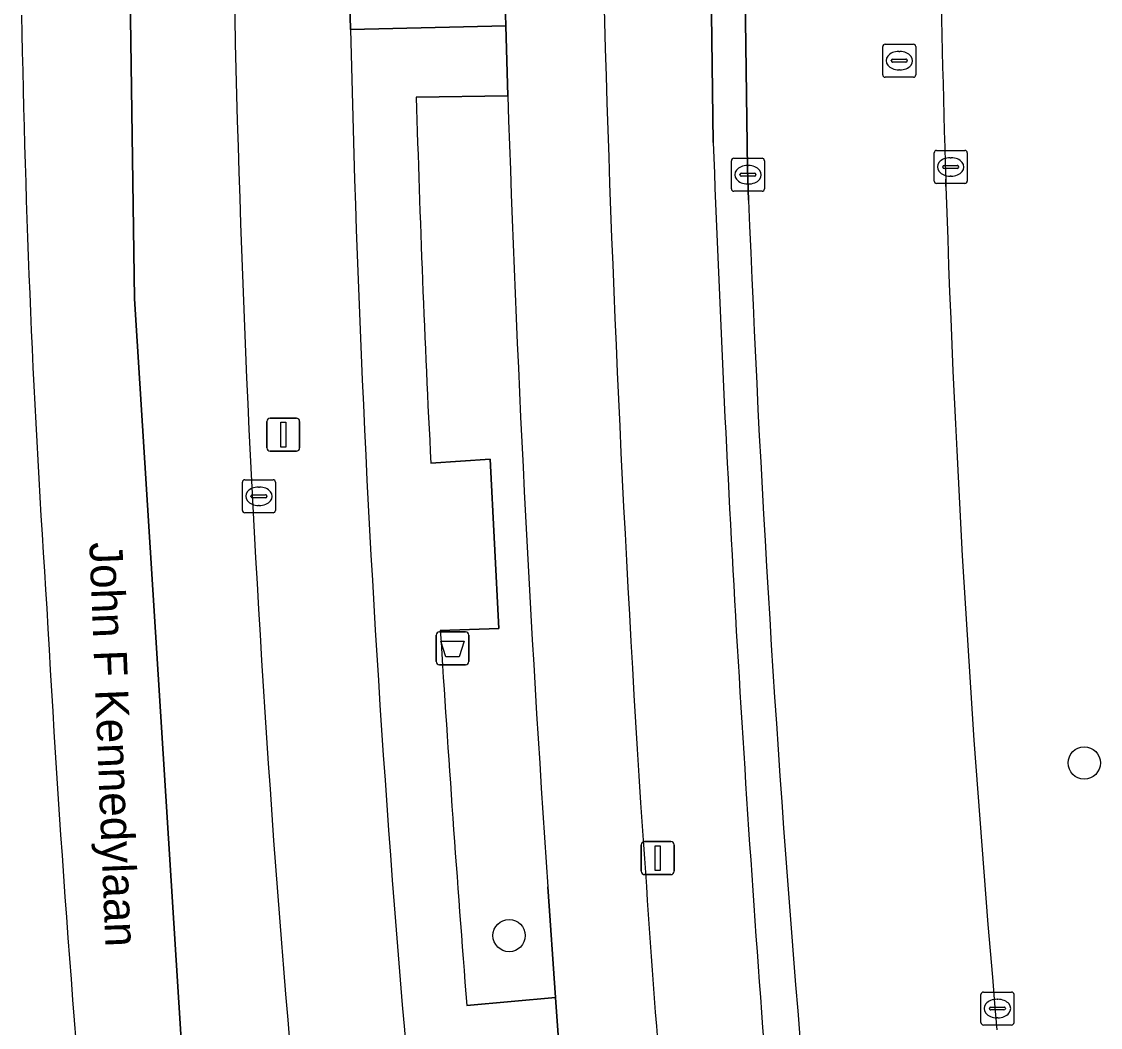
# Model space of a CAD drawing. Extents: x 161477 to 163040, y 383680 to 384871.
# Drawn here: x 161509.36 to 161542, y 384062.14 to 384092.59 of the extents above; entities that cross this region are included whole.
import ezdxf

# ---------------------------------------------------------------- set-up
doc = ezdxf.new("R2010")
doc.units = 0
for name, color, linetype in [('IMGEO_Afvalbak', 7, 'Continuous'), ('IMGEO_Berm_groen', 7, 'Continuous'), ('IMGEO_Boom', 7, 'Continuous'), ('IMGEO_Fietspad_open', 7, 'Continuous'), ('IMGEO_Groenvoorziening', 7, 'Continuous'), ('IMGEO_Kolk', 7, 'Continuous'), ('IMGEO_Lichtmast', 7, 'Continuous'), ('IMGEO_Openbare_ruimte_label', 7, 'Continuous'), ('IMGEO_OVBaan_gesloten', 7, 'Continuous'), ('IMGEO_Rijbaan_lokaal_gesloten', 7, 'Continuous'), ('IMGEO_Rijbaan_lokaal_open', 7, 'Continuous'), ('IMGEO_Rioolput', 7, 'Continuous'), ('IMGEO_Verkeerseiland_groen', 7, 'Continuous'), ('IMGEO_Voetpad_open', 7, 'Continuous')]:
    doc.layers.add(name, color=color, linetype=linetype)

msp = doc.modelspace()

# ---------------------------------------------------------------- linework, layer by layer
at = {"layer": 'IMGEO_Afvalbak'}
for p, q in [((161522.002, 384074.118), (161522.792, 384074.118)), ((161522.792, 384074.118), (161522.002, 384074.118)), ((161521.902, 384073.218), (161521.902, 384074.018)), ((161521.902, 384074.018), (161521.902, 384073.218)), ((161522.892, 384074.018), (161522.892, 384073.218)), ((161522.892, 384073.218), (161522.892, 384074.018)), ((161522.792, 384073.118), (161522.002, 384073.118)), ((161522.002, 384073.118), (161522.792, 384073.118))]:
    msp.add_line(p, q, dxfattribs=at)
msp.add_lwpolyline([(161522.045, 384073.832), (161522.749, 384073.832), (161522.6, 384073.362), (161522.194, 384073.362), (161522.045, 384073.832)], dxfattribs=at)
for centre, start, end in [((161522.002, 384074.018), 90, 180), ((161522.002, 384074.018), 90, 180), ((161522.792, 384074.018), 0, 90), ((161522.792, 384074.018), 360, 90), ((161522.002, 384073.218), 180, 270), ((161522.002, 384073.218), 180, 270), ((161522.792, 384073.218), 270, 0), ((161522.792, 384073.218), 270, 0)]:
    msp.add_arc(centre, 0.1, start, end, dxfattribs=at)
at = {"layer": 'IMGEO_Berm_groen'}
msp.add_lwpolyline([(161519.286, 384093.326), (161519.293, 384093.147), (161519.31, 384092.356), (161524.006, 384092.467), (161523.996, 384092.805), (161523.824, 384101.994)], dxfattribs=at)
for centre, radius, start, end in [((161870.69, 384099.146), 361.389, 181.00836, 183.85803), ((162020.3, 384102.502), 510.93, 183.10469, 185.34779)]:
    msp.add_arc(centre, radius, start, end, dxfattribs=at)
at = {"layer": 'IMGEO_Boom'}
for centre in [(161541.513, 384070.146), (161524.109, 384064.919)]:
    msp.add_circle(centre, 0.489, dxfattribs=at)
at = {"layer": 'IMGEO_Fietspad_open'}
for points in [[(161515.721, 384110.468), (161523.848, 384110.651), (161523.758, 384107.222), (161523.769, 384107.113), (161523.788, 384106.113), (161523.681, 384106.114), (161523.824, 384101.994), (161523.996, 384092.805), (161524.006, 384092.467), (161524.071, 384090.349)], [(161525.28, 384066.396), (161525.511, 384063.044), (161525.665, 384060.913)]]:
    msp.add_lwpolyline(points, dxfattribs=at)
for centre, radius, start, end in [((162194.711, 384111.674), 667.99, 181.427877, 183.668064), ((162190.499, 384111.979), 666.779, 181.85899, 183.919982), ((162521.881, 384135.354), 996.008, 183.823363, 185.383124)]:
    msp.add_arc(centre, radius, start, end, dxfattribs=at)
at = {"layer": 'IMGEO_Groenvoorziening'}
for points in [[(161531.356, 384087.19), (161531.32, 384088.12), (161531.174, 384099.384), (161530.14, 384099.502), (161530.155, 384099.073), (161530.287, 384088.932)], [(161537.32, 384087.82), (161537.327, 384087.599)]]:
    msp.add_lwpolyline(points, dxfattribs=at)
for centre, radius, start, end in [((162047.346, 384103.272), 510.26, 179.99265, 181.73528), ((162231.505, 384114.608), 701.688, 182.097053, 184.515444), ((161984.51, 384101.846), 447.41, 181.82484, 185.10092), ((162116.096, 384110.255), 585.195, 182.258894, 184.745135)]:
    msp.add_arc(centre, radius, start, end, dxfattribs=at)
at = {"layer": 'IMGEO_Kolk'}
for p, q in [((161530.911, 384088.455), (161531.763, 384088.455)), ((161536.97, 384087.765), (161536.97, 384088.617)), ((161537.045, 384088.691), (161537.897, 384088.691)), ((161537.458, 384088.471), (161537.483, 384088.471)), ((161537.971, 384088.617), (161537.971, 384087.765)), ((161530.836, 384087.529), (161530.836, 384088.381)), ((161531.324, 384088.235), (161531.349, 384088.235)), ((161531.837, 384088.381), (161531.837, 384087.529)), ((161537.229, 384088.185), (161537.229, 384088.197)), ((161537.667, 384088.148), (161537.269, 384088.148)), ((161537.272, 384088.234), (161537.67, 384088.234)), ((161537.713, 384088.197), (161537.713, 384088.185)), ((161531.095, 384087.949), (161531.095, 384087.961)), ((161531.533, 384087.912), (161531.135, 384087.912)), ((161531.138, 384087.998), (161531.536, 384087.998)), ((161531.579, 384087.961), (161531.579, 384087.949)), ((161537.481, 384087.911), (161537.456, 384087.911)), ((161531.347, 384087.675), (161531.322, 384087.675)), ((161537.897, 384087.691), (161537.045, 384087.691)), ((161531.763, 384087.455), (161530.911, 384087.455)), ((161516.039, 384077.794), (161516.039, 384078.646)), ((161516.114, 384078.72), (161516.966, 384078.72)), ((161517.04, 384078.646), (161517.04, 384077.794)), ((161516.527, 384078.5), (161516.552, 384078.5)), ((161516.298, 384078.214), (161516.298, 384078.226)), ((161516.736, 384078.177), (161516.338, 384078.177)), ((161516.341, 384078.263), (161516.739, 384078.263)), ((161516.782, 384078.226), (161516.782, 384078.214)), ((161516.966, 384077.72), (161516.114, 384077.72)), ((161516.55, 384077.94), (161516.525, 384077.94)), ((161538.386, 384062.285), (161538.386, 384063.137)), ((161538.461, 384063.211), (161539.313, 384063.211)), ((161538.874, 384062.991), (161538.899, 384062.991)), ((161539.387, 384063.137), (161539.387, 384062.285)), ((161538.645, 384062.705), (161538.645, 384062.717)), ((161539.083, 384062.668), (161538.685, 384062.668)), ((161538.688, 384062.754), (161539.086, 384062.754)), ((161539.129, 384062.717), (161539.129, 384062.705)), ((161538.897, 384062.431), (161538.872, 384062.431)), ((161539.313, 384062.211), (161538.461, 384062.211))]:
    msp.add_line(p, q, dxfattribs=at)
for points in [[(161530.911, 384088.455), (161531.763, 384088.455)], [(161536.97, 384087.765), (161536.97, 384088.617)], [(161537.045, 384088.691), (161537.897, 384088.691)], [(161537.971, 384088.617), (161537.971, 384087.765)], [(161530.836, 384087.529), (161530.836, 384088.381)], [(161531.837, 384088.381), (161531.837, 384087.529)], [(161537.897, 384087.691), (161537.045, 384087.691)], [(161531.763, 384087.455), (161530.911, 384087.455)], [(161516.039, 384077.794), (161516.039, 384078.646)], [(161516.114, 384078.72), (161516.966, 384078.72)], [(161517.04, 384078.646), (161517.04, 384077.794)], [(161516.966, 384077.72), (161516.114, 384077.72)], [(161538.386, 384062.285), (161538.386, 384063.137)], [(161538.461, 384063.211), (161539.313, 384063.211)], [(161539.387, 384063.137), (161539.387, 384062.285)], [(161539.313, 384062.211), (161538.461, 384062.211)]]:
    msp.add_lwpolyline(points, dxfattribs=at)
for centre, radius, start, end in [((161530.913, 384088.379), 0.0765, 91.552, 178.448), ((161530.913, 384088.379), 0.0765, 91.552, 178.448), ((161531.761, 384088.379), 0.0765, 1.552, 88.448), ((161531.761, 384088.379), 0.0765, 1.552, 88.448), ((161537.047, 384088.615), 0.0765, 91.552, 178.448), ((161537.047, 384088.615), 0.0765, 91.552, 178.448), ((161537.895, 384088.615), 0.0765, 1.552, 88.448), ((161537.895, 384088.615), 0.0765, 1.552, 88.448), ((161537.269, 384088.194), 0.0403, 85.8775, 175.7526), ((161537.266, 384088.184), 0.0366, 178.938, 274.7102), ((161537.67, 384088.191), 0.043, 264.8664, 352.4533), ((161537.674, 384088.196), 0.0386, 1.7309, 96.639), ((161531.135, 384087.958), 0.0403, 85.8775, 175.7526), ((161531.132, 384087.948), 0.0366, 178.938, 274.7102), ((161531.536, 384087.955), 0.043, 264.8664, 352.4533), ((161531.54, 384087.96), 0.0386, 1.7309, 96.639), ((161530.913, 384087.531), 0.0765, 181.552, 268.448), ((161530.913, 384087.531), 0.0765, 181.552, 268.448), ((161531.761, 384087.531), 0.0765, 271.552, 358.448), ((161531.761, 384087.531), 0.0765, 271.552, 358.448), ((161537.047, 384087.767), 0.0765, 181.552, 268.448), ((161537.047, 384087.767), 0.0765, 181.552, 268.448), ((161537.895, 384087.767), 0.0765, 271.552, 358.448), ((161537.895, 384087.767), 0.0765, 271.552, 358.448), ((161516.116, 384078.644), 0.0765, 91.552, 178.448), ((161516.116, 384078.644), 0.0765, 91.552, 178.448), ((161516.964, 384078.644), 0.0765, 1.552, 88.448), ((161516.964, 384078.644), 0.0765, 1.552, 88.448), ((161516.338, 384078.223), 0.0403, 85.8775, 175.7526), ((161516.335, 384078.213), 0.0366, 178.938, 274.7102), ((161516.739, 384078.22), 0.043, 264.8664, 352.4533), ((161516.743, 384078.225), 0.0386, 1.7309, 96.639), ((161516.116, 384077.796), 0.0765, 181.552, 268.448), ((161516.116, 384077.796), 0.0765, 181.552, 268.448), ((161516.964, 384077.796), 0.0765, 271.552, 358.448), ((161516.964, 384077.796), 0.0765, 271.552, 358.448), ((161538.463, 384063.135), 0.0765, 91.552, 178.448), ((161538.463, 384063.135), 0.0765, 91.552, 178.448), ((161539.311, 384063.135), 0.0765, 1.552, 88.448), ((161539.311, 384063.135), 0.0765, 1.552, 88.448), ((161538.685, 384062.714), 0.0403, 85.8775, 175.7526), ((161538.682, 384062.704), 0.0366, 178.938, 274.7102), ((161539.086, 384062.711), 0.043, 264.8664, 352.4533), ((161539.09, 384062.716), 0.0386, 1.7309, 96.639), ((161538.463, 384062.287), 0.0765, 181.552, 268.448), ((161538.463, 384062.287), 0.0765, 181.552, 268.448), ((161539.311, 384062.287), 0.0765, 271.552, 358.448), ((161539.311, 384062.287), 0.0765, 271.552, 358.448)]:
    msp.add_arc(centre, radius, start, end, dxfattribs=at)
for centre, major_axis, ratio, start_param, end_param in [((161537.457, 384088.191), (-0.387, 0.002), 0.722429, 4.712389, 7.853982), ((161537.482, 384088.191), (-0.39, 0.002), 0.717154, 1.570796, 4.712389), ((161531.323, 384087.955), (-0.387, 0.002), 0.722429, 4.712389, 7.853982), ((161531.348, 384087.955), (-0.39, 0.002), 0.717154, 1.570796, 4.712389), ((161516.526, 384078.22), (-0.387, 0.002), 0.722429, 4.712389, 7.853982), ((161516.551, 384078.22), (-0.39, 0.002), 0.717154, 1.570796, 4.712389), ((161538.873, 384062.711), (-0.387, 0.002), 0.722429, 4.712389, 7.853982), ((161538.898, 384062.711), (-0.39, 0.002), 0.717154, 1.570796, 4.712389)]:
    msp.add_ellipse(centre, major_axis=major_axis, ratio=ratio, start_param=start_param, end_param=end_param, dxfattribs=at)
at = {"layer": 'IMGEO_Lichtmast'}
for p, q in [((161516.781, 384079.687), (161516.781, 384080.487)), ((161516.781, 384080.487), (161516.781, 384079.687)), ((161516.881, 384080.587), (161517.671, 384080.587)), ((161517.671, 384080.587), (161516.881, 384080.587)), ((161517.771, 384080.487), (161517.771, 384079.687)), ((161517.771, 384079.687), (161517.771, 384080.487)), ((161517.671, 384079.587), (161516.881, 384079.587)), ((161516.881, 384079.587), (161517.671, 384079.587)), ((161528.11, 384066.866), (161528.11, 384067.666)), ((161528.11, 384067.666), (161528.11, 384066.866)), ((161528.21, 384067.766), (161529, 384067.766)), ((161529, 384067.766), (161528.21, 384067.766)), ((161529.1, 384067.666), (161529.1, 384066.866)), ((161529.1, 384066.866), (161529.1, 384067.666)), ((161529, 384066.766), (161528.21, 384066.766)), ((161528.21, 384066.766), (161529, 384066.766))]:
    msp.add_line(p, q, dxfattribs=at)
for points in [[(161517.201, 384080.462), (161517.351, 384080.462), (161517.351, 384079.712), (161517.201, 384079.712), (161517.201, 384080.462)], [(161528.53, 384067.641), (161528.68, 384067.641), (161528.68, 384066.891), (161528.53, 384066.891), (161528.53, 384067.641)]]:
    msp.add_lwpolyline(points, dxfattribs=at)
for centre, start, end in [((161516.881, 384080.487), 90, 180), ((161516.881, 384080.487), 90, 180), ((161517.671, 384080.487), 0, 90), ((161517.671, 384080.487), 360, 90), ((161516.881, 384079.687), 180, 270), ((161516.881, 384079.687), 180, 270), ((161517.671, 384079.687), 270, 0), ((161517.671, 384079.687), 270, 0), ((161528.21, 384067.666), 90, 180), ((161528.21, 384067.666), 90, 180), ((161529, 384067.666), 0, 90), ((161529, 384067.666), 360, 90), ((161528.21, 384066.866), 180, 270), ((161528.21, 384066.866), 180, 270), ((161529, 384066.866), 270, 0), ((161529, 384066.866), 270, 0)]:
    msp.add_arc(centre, 0.1, start, end, dxfattribs=at)
at = {"layer": 'IMGEO_OVBaan_gesloten'}
msp.add_lwpolyline([(161519.31, 384092.356), (161519.293, 384093.147), (161519.286, 384093.326)], dxfattribs=at)
for centre, radius, start, end in [((162006.795, 384103.458), 491.106, 181.16373, 186.98146), ((162003.689, 384103.252), 484.502, 181.28861, 187.02918)]:
    msp.add_arc(centre, radius, start, end, dxfattribs=at)
at = {"layer": 'IMGEO_Rijbaan_lokaal_gesloten'}
for points in [[(161531.069, 384114.824), (161531.071, 384114.592), (161531.061, 384111.456), (161531.125, 384103.186), (161531.174, 384099.384), (161531.32, 384088.12), (161531.356, 384087.19)], [(161511.594, 384054.883), (161513.763, 384035.93), (161515.753, 384021.118), (161516.416, 384015.919), (161516.652, 384013.931), (161519.658, 384016.476), (161516.91, 384036.302), (161514.276, 384060.331), (161512.771, 384084.199), (161512.45, 384106.854)], [(161515.79, 384093.484), (161515.72, 384103.46), (161515.722, 384103.553), (161515.725, 384103.707), (161515.723, 384104.415), (161515.721, 384105.139), (161515.719, 384106.934), (161512.45, 384106.854), (161512.771, 384084.199), (161514.276, 384060.331), (161516.91, 384036.302), (161519.658, 384016.476), (161522.583, 384018.952), (161522.042, 384023.134), (161521.992, 384023.395), (161520.306, 384036.379), (161519.33, 384043.765)], [(161537.327, 384087.599), (161537.32, 384087.82)]]:
    msp.add_lwpolyline(points, dxfattribs=at)
for centre, radius, start, end in [((162047.346, 384103.272), 510.26, 179.99265, 181.73528), ((162006.795, 384103.458), 491.106, 181.16373, 186.98146), ((161870.69, 384099.146), 361.389, 181.00836, 183.85803), ((161984.51, 384101.846), 447.41, 181.82484, 185.10092), ((162116.096, 384110.255), 585.195, 182.258894, 184.745135), ((162020.3, 384102.502), 510.93, 183.10469, 185.34779)]:
    msp.add_arc(centre, radius, start, end, dxfattribs=at)
at = {"layer": 'IMGEO_Rijbaan_lokaal_open'}
for points in [[(161521.302, 384090.299), (161524.071, 384090.349), (161524.006, 384092.467), (161519.31, 384092.356)], [(161523.534, 384079.342), (161521.741, 384079.227)], [(161522.026, 384074.158), (161523.8, 384074.218), (161523.534, 384079.342)], [(161523.373, 384056.802), (161525.156, 384056.968), (161524.851, 384060.863), (161525.665, 384060.913), (161525.511, 384063.044), (161522.828, 384062.803)]]:
    msp.add_lwpolyline(points, dxfattribs=at)
for centre, radius, start, end in [((162003.689, 384103.252), 484.502, 181.28861, 187.02918), ((161990.633, 384103.363), 469.513, 181.59445, 182.94668), ((162296.446, 384123.149), 775.968, 183.619811, 184.460335)]:
    msp.add_arc(centre, radius, start, end, dxfattribs=at)
at = {"layer": 'IMGEO_Rioolput'}
for p, q in [((161535.416, 384090.982), (161535.416, 384091.834)), ((161535.491, 384091.908), (161536.343, 384091.908)), ((161536.417, 384091.834), (161536.417, 384090.982)), ((161535.675, 384091.402), (161535.675, 384091.414)), ((161535.718, 384091.451), (161536.116, 384091.451)), ((161535.904, 384091.688), (161535.929, 384091.688)), ((161536.159, 384091.414), (161536.159, 384091.402)), ((161536.113, 384091.365), (161535.715, 384091.365)), ((161535.927, 384091.128), (161535.902, 384091.128)), ((161536.343, 384090.908), (161535.491, 384090.908))]:
    msp.add_line(p, q, dxfattribs=at)
for points in [[(161535.416, 384090.982), (161535.416, 384091.834)], [(161535.491, 384091.908), (161536.343, 384091.908)], [(161536.417, 384091.834), (161536.417, 384090.982)], [(161536.343, 384090.908), (161535.491, 384090.908)]]:
    msp.add_lwpolyline(points, dxfattribs=at)
for centre, radius, start, end in [((161535.493, 384091.832), 0.0765, 91.552, 178.448), ((161535.493, 384091.832), 0.0765, 91.552, 178.448), ((161536.341, 384091.832), 0.0765, 1.552, 88.448), ((161536.341, 384091.832), 0.0765, 1.552, 88.448), ((161535.715, 384091.411), 0.0403, 85.8775, 175.7526), ((161535.712, 384091.401), 0.0366, 178.938, 274.7102), ((161536.116, 384091.408), 0.043, 264.8664, 352.4533), ((161536.12, 384091.413), 0.0386, 1.7309, 96.639), ((161535.493, 384090.984), 0.0765, 181.552, 268.448), ((161535.493, 384090.984), 0.0765, 181.552, 268.448), ((161536.341, 384090.984), 0.0765, 271.552, 358.448), ((161536.341, 384090.984), 0.0765, 271.552, 358.448)]:
    msp.add_arc(centre, radius, start, end, dxfattribs=at)
for centre, major_axis, ratio, start_param, end_param in [((161535.903, 384091.408), (-0.387, 0.002), 0.722429, 4.712389, 7.853982), ((161535.928, 384091.408), (-0.39, 0.002), 0.717154, 1.570796, 4.712389)]:
    msp.add_ellipse(centre, major_axis=major_axis, ratio=ratio, start_param=start_param, end_param=end_param, dxfattribs=at)
at = {"layer": 'IMGEO_Verkeerseiland_groen'}
for points in [[(161524.071, 384090.349), (161521.302, 384090.299)], [(161521.741, 384079.227), (161523.534, 384079.342), (161523.8, 384074.218), (161522.026, 384074.158)], [(161522.828, 384062.803), (161525.511, 384063.044), (161525.28, 384066.396)]]:
    msp.add_lwpolyline(points, dxfattribs=at)
for centre, radius, start, end in [((161990.633, 384103.363), 469.513, 181.59445, 182.94668), ((162190.499, 384111.979), 666.779, 181.85899, 183.919982), ((162296.446, 384123.149), 775.968, 183.619811, 184.460335)]:
    msp.add_arc(centre, radius, start, end, dxfattribs=at)
at = {"layer": 'IMGEO_Voetpad_open'}
msp.add_lwpolyline([(161530.287, 384088.932), (161530.155, 384099.073), (161530.14, 384099.502), (161529.874, 384107.039), (161530.064, 384116.948)], dxfattribs=at)
for centre, radius, start, end in [((162194.711, 384111.674), 667.99, 181.427877, 183.668064), ((162231.505, 384114.608), 701.688, 182.097053, 184.515444), ((162521.881, 384135.354), 996.008, 183.823363, 185.383124)]:
    msp.add_arc(centre, radius, start, end, dxfattribs=at)

# ---------------------------------------------------------------- texts
at = {"layer": 'IMGEO_Openbare_ruimte_label'}
msp.add_text('John F Kennedylaan', height=1, rotation=272.2929, dxfattribs=at).set_placement((161511.406, 384076.82))

doc.saveas('drawing.dxf')
